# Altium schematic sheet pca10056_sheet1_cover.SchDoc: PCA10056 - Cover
size A3; Organization: Nordic Semiconductor; DocumentNumber: 1; SheetNumber: 1; SheetTotal: 7; CompanyName: Nordic Semiconductor
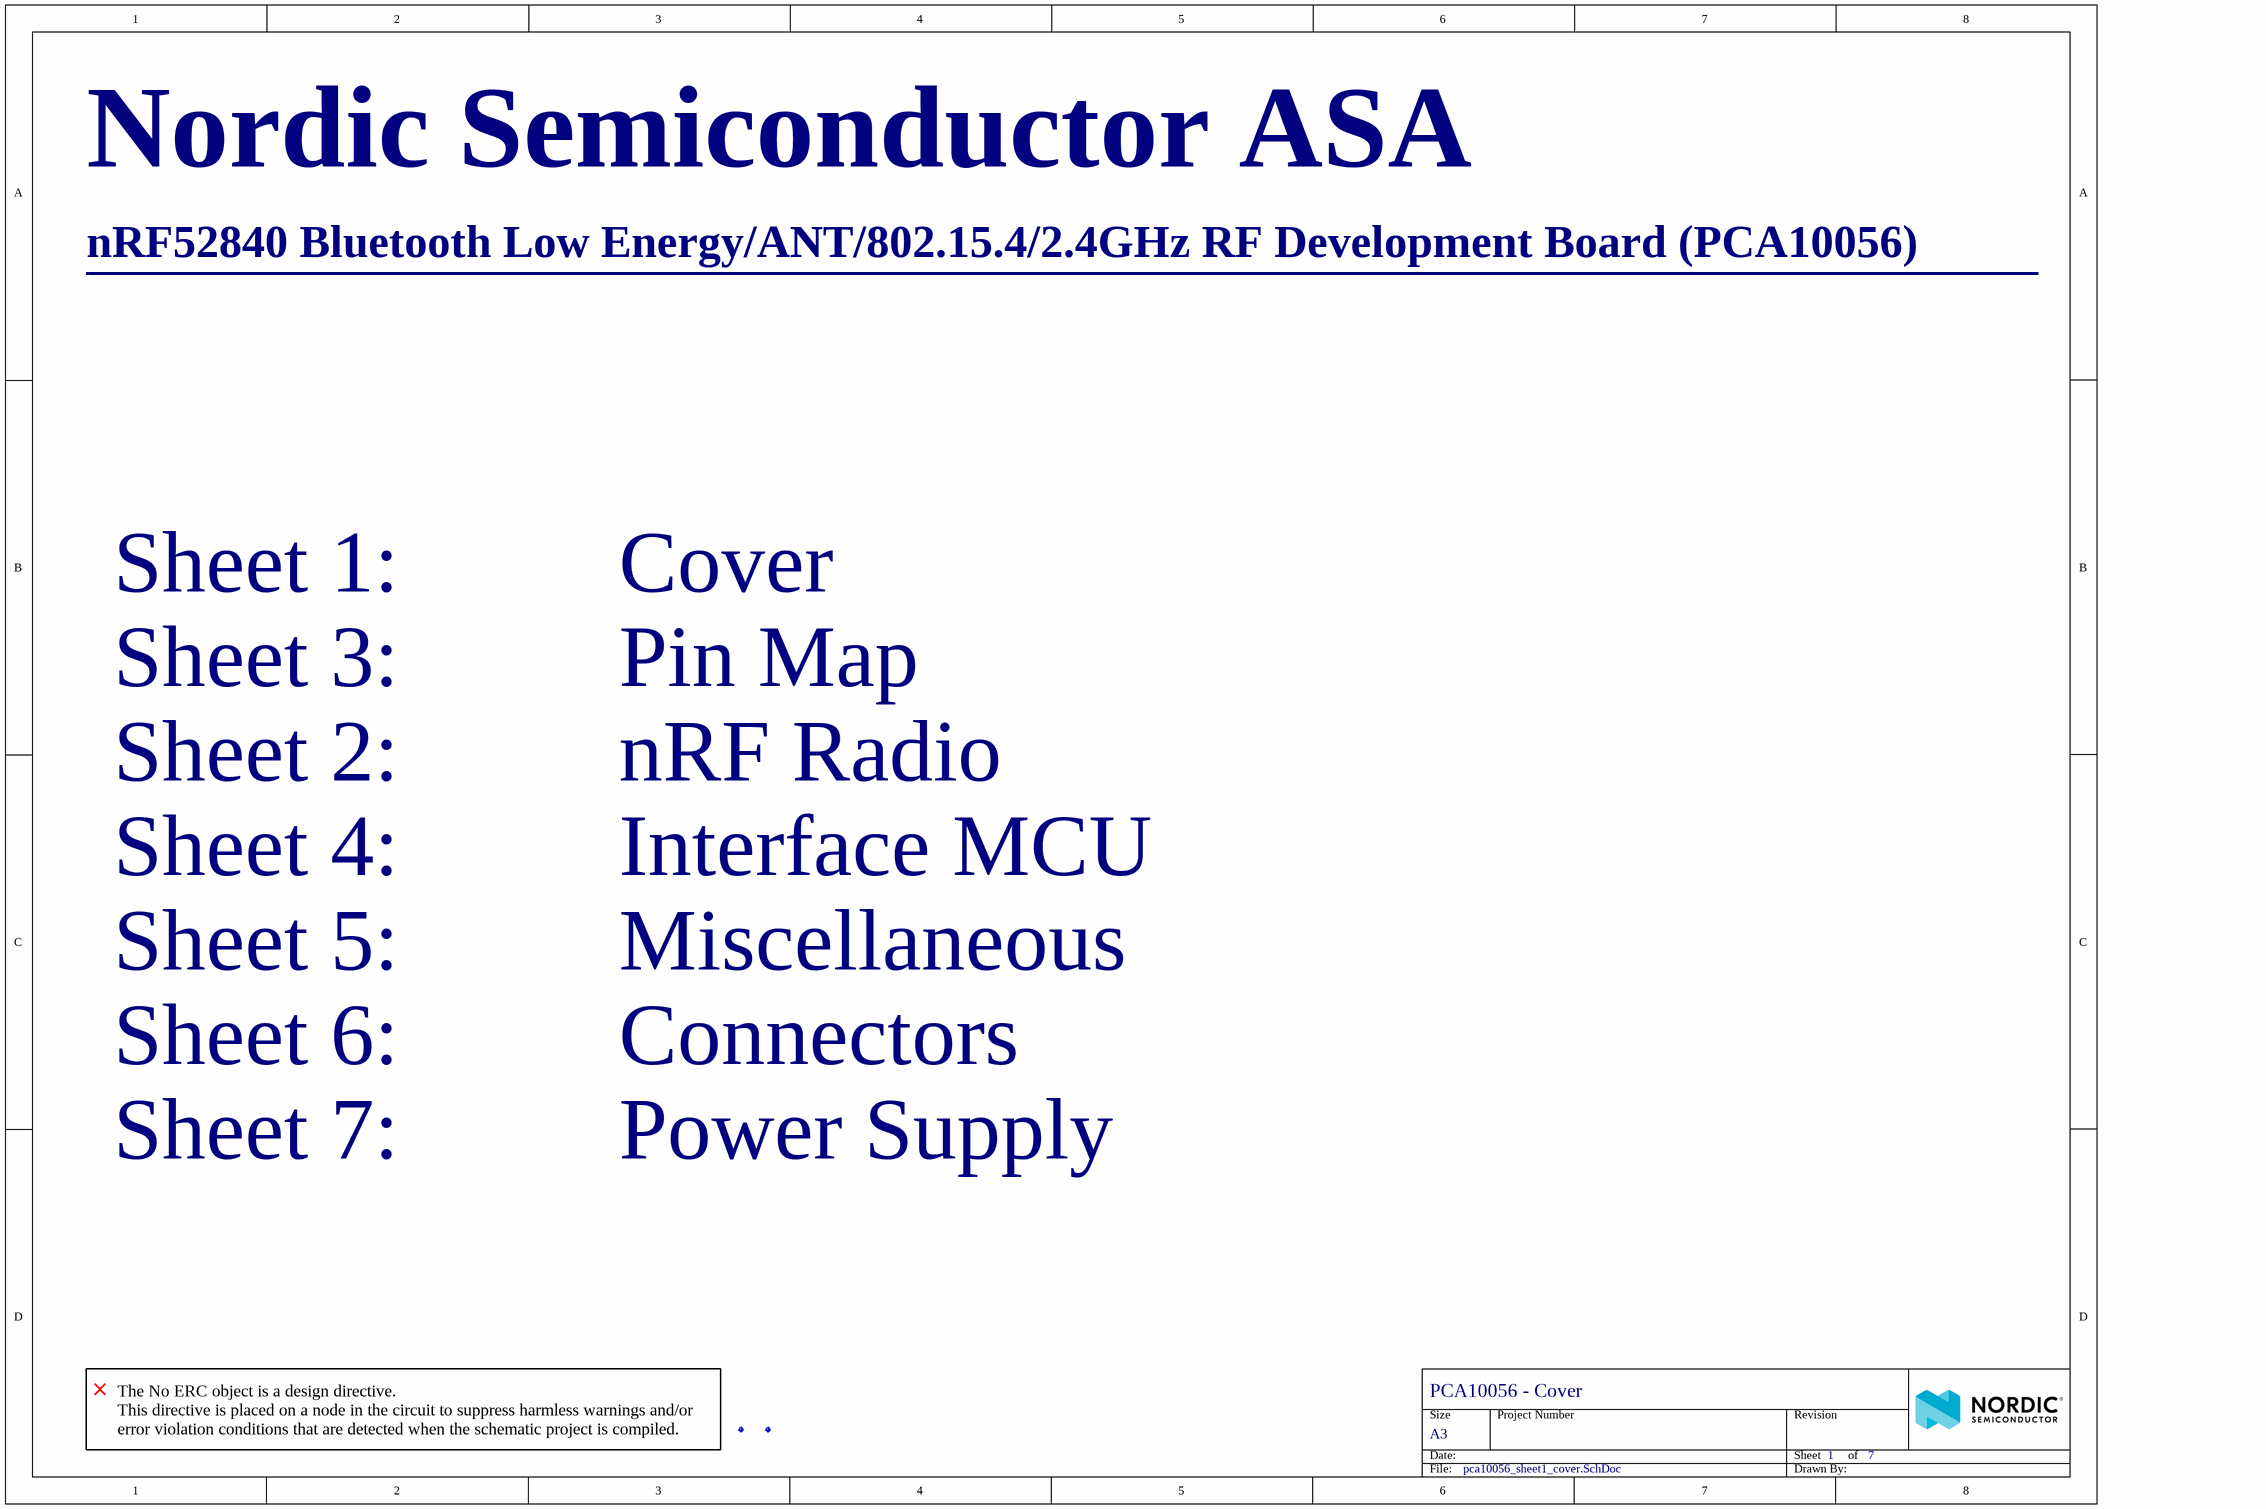
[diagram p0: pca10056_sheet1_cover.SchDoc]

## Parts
Fid1  Fiducial mark  [Fiducial]  (value not drawn)
Fid2  Fiducial mark  [Fiducial]  (value not drawn)

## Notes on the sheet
- Nordic Semiconductor ASA
- nRF52840 Bluetooth Low Energy/ANT/802.15.4/2.4GHz RF Development Board (PCA10056)
- ________________________________________________________________
- Sheet 1:          Cover
- Sheet 3:          Pin Map
- Sheet 2:          nRF Radio
- Sheet 4:          Interface MCU
- Sheet 5:          Miscellaneous
- Sheet 6:          Connectors
- Sheet 7:          Power Supply
- (near Fid1) The No ERC object is a design directive.
  This directive is placed on a node in the circuit to suppress harmless warnings and/or error violation conditions that are detected when the schematic project is compiled.

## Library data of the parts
Fid1 Fid2 = Fid-Mark: Artikkelnr Noca: N.A.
